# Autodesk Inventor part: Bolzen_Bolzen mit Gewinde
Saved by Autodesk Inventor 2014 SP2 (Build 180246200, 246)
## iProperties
Created: 2015-07
Part Number: Bolzen_Bolzen mit Gewinde
Material: Generisch
Document SubType Name: Modeling
Designer: e_krauts
Density: 1 g/cm^3
Appearance: Vorgabe
Author: e_krauts
Sending System: SolidWorks 2011
Last Author: e_boekem
Erstellt durch: XYZ
Werkstoff: AlCu4PbMg
Einheit: Stck.
UNIT_OF_MEASURE: Sachnummer
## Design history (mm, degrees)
node "Bolzen_Bolzen mit Gewinde.ipt1"
node "M8 Gewindebohrung1"
node "Basis1"
